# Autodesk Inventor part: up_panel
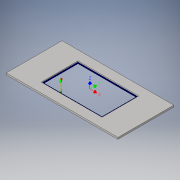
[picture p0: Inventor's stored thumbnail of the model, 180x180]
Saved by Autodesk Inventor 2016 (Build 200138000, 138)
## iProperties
Created: 2017-01
Part Number: up_panel
Material: Типовые
Document SubType Name: Modeling
Designer: admin
Density: 1 g/cm^3
Appearance: По умолчанию
Author: admin
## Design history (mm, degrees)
sketch "Эскиз1"
  geometry: L1 (-100, -50)-(100, -50); L2 (100, -50)-(100, 50); L3 (100, 50)-(-100, 50); L4 (-100, 50)-(-100, -50); L5 (-100, -50)-(100, 50); L6 (100, -50)-(-100, 50); 1 further point
  constraints: 12 end point, 2 midpoint, 2 parallel, 1 horizontal, 1 perpendicular
  dimensions: "d0" = 200 distance of L3.end L2.end; "d1" = 100 distance of L2.end L1.end
extrude "Выдавливание1" new body sketch "Эскиз1" distance "d2" = 3; taper "d3" = 0 deg
sketch "Эскиз2"
  geometry: L1 (-54.5, -33)-(54.5, -33); L2 (54.5, -33)-(54.5, 33); L3 (54.5, 33)-(-54.5, 33); L4 (-54.5, 33)-(-54.5, -33); L5 (-54.5, -33)-(54.5, 33); L6 (54.5, -33)-(-54.5, 33); 1 further point
  constraints: 12 end point, 2 midpoint, 2 parallel, 1 horizontal, 1 perpendicular
  dimensions: "d4" = 109 distance of L3.end L2.end; "d5" = 66 distance of L2.end L1.end
extrude "Выдавливание2" cut sketch "Эскиз2" distance "d6" = 3; taper "d7" = 0 deg
node "Твердое тело1"
